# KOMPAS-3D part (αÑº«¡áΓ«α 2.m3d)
File: created 06.04.2016 12:01:11, last saved 07.04.2016 18:23:20.
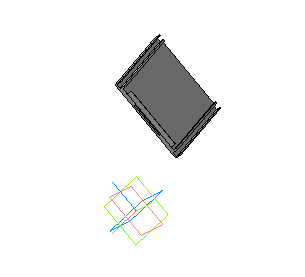
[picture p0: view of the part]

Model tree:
1. Эскиз:1
2. Операция выдавливания:1
     Толщина стенки 1 = 2; Толщина стенки 2 = 6; Расстояние 1 = 1
3. Эскиз:2
4. Операция выдавливания:2
     Толщина стенки 1 = 2; Толщина стенки 2 = 7; Расстояние 1 = 5
5. Эскиз:3
6. Операция выдавливания:3
     Толщина стенки 1 = 2; Толщина стенки 2 = 6; Расстояние 1 = 2
7. Эскиз:4
8. Операция выдавливания:4
     Толщина стенки 1 = 2; Толщина стенки 2 = 2.5; Расстояние 1 = 60
9. Эскиз:5
10. Вырезать элемент выдавливания:1
     Толщина стенки 2 = 1.5; Расстояние 1 = 40
11. Эскиз:6
12. Операция выдавливания:5
     Толщина стенки 1 = 2; Толщина стенки 2 = 2.5; Расстояние 1 = 20
13. Эскиз:7
14. Операция выдавливания:6
     Толщина стенки 1 = 2; Толщина стенки 2 = 6; Расстояние 1 = 2
15. Эскиз:8
16. Операция выдавливания:7
     Толщина стенки 1 = 2; Толщина стенки 2 = 6; Расстояние 1 = 5
17. Эскиз:9
18. Операция выдавливания:8
     Толщина стенки 1 = 2; Толщина стенки 2 = 6; Расстояние 1 = 1
19. Эскиз:10
20. Вырезать элемент выдавливания:2
     Толщина стенки 2 = 1.5; Расстояние 1 = 22
21. Эскиз:11
22. Вырезать элемент выдавливания:3
     Толщина стенки 2 = 1.5; Расстояние 1 = 1
23. Скругление:4
     Радиус = 1
24. Эскиз:12
25. Вырезать элемент выдавливания:4
     Расстояние 1 = 110
26. Эскиз:13
27. Операция выдавливания:9
     Толщина стенки 1 = 6; Толщина стенки 2 = 2.5; Расстояние 1 = 60; Расстояние 2 = 0.4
